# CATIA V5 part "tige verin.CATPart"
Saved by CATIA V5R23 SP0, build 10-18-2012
Part number: tige verin
Definition: tige verin
Source: made
Bounding box of the stored display mesh (mm): x -42 to 232, y -13 to 13, z -13 to 13
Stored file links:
  C:\wamp\www\COURS\CONCEPTION GMP1\TITRE 01-CATIA VOLUMIQUE\05--ACTIONNEUR DE VANNE\prof\CORRECTION\Assemblage\tige verin.CATPart
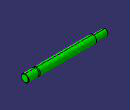
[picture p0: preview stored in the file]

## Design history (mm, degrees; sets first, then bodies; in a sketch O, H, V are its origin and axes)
Set1
  Plane1: type OffsetPt, RefPlane yz-plane, RefPoint {point type Center, Curve edge [face of Solid1 | face of Solid1]}
  Plane2: type Offset, RefPlane yz-plane, Offset 196
Body1 "NONE" (main body)
  Solid1 "Manifold Solid #3015": solid without history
